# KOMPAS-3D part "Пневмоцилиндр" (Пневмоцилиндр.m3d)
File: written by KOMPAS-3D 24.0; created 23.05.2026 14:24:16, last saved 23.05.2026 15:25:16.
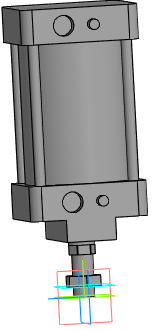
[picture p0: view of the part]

Document properties: Автор: R2D2; Полное имя файла: E:\Работа\Зайцев\GVKR1331M-1W-Fb-2P Задвижка шиберная с выдвижным штоком DN.ru Ду50-300 Ру16-10-6 с пневмоприводом\исходные материалы\DN65\Пневмоцилиндр.m3d

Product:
- Part/product: Пневмоцилиндр
    Масса: 16.00327

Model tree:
1. Эскиз:1
2. Элемент выдавливания:1
3. Смещенная плоскость:1
4. Эскиз:2
5. Элемент выдавливания:2
6. Эскиз:3  (with: Грань.Элемент выдавливания:1)
7. Элемент выдавливания:3
8. Эскиз:4  (with: Грань.Элемент выдавливания:3)
9. Элемент выдавливания:4  (with: Грань.Элемент выдавливания:3)
     Расстояние 2 = 9; Смещение 2 = 5
10. Эскиз:5  (with: Грань.Элемент выдавливания:3)
11. Элемент выдавливания:5
12. Эскиз:6  (with: Грань.Элемент выдавливания:5)
13. Элемент выдавливания:6
14. Эскиз:7  (with: Грань.Элемент выдавливания:6)
15. Элемент выдавливания:7
16. Эскиз:8  (with: Грань.Элемент выдавливания:7, Ребро.Элемент выдавливания:6)
17. Элемент выдавливания:8
18. Эскиз:9  (with: Грань.Элемент выдавливания:6, Вершина.Элемент выдавливания:8)
19. Элемент выдавливания:9  (with: Грань.Элемент выдавливания:8)
     Расстояние 1 = 133
20. Массив по концентрической сетке:1  (with: Элемент выдавливания:9, Эскиз:9)  (4 pattern instances)
     Шаг 2 = 360
21. Скругление:1  (with: Ребро.Элемент выдавливания:6, Ребро.Элемент выдавливания:8)
     Радиус = 10
22. Эскиз:10  (with: Грань.Элемент выдавливания:5, Ребро.Элемент выдавливания:6, Ребро.Элемент выдавливания:8)
23. Элемент выдавливания:10
24. Эскиз:11  (with: Грань.Элемент выдавливания:5, Ребро.Элемент выдавливания:10)
25. Элемент выдавливания:11

Expressions: k/2; c-2*g+x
